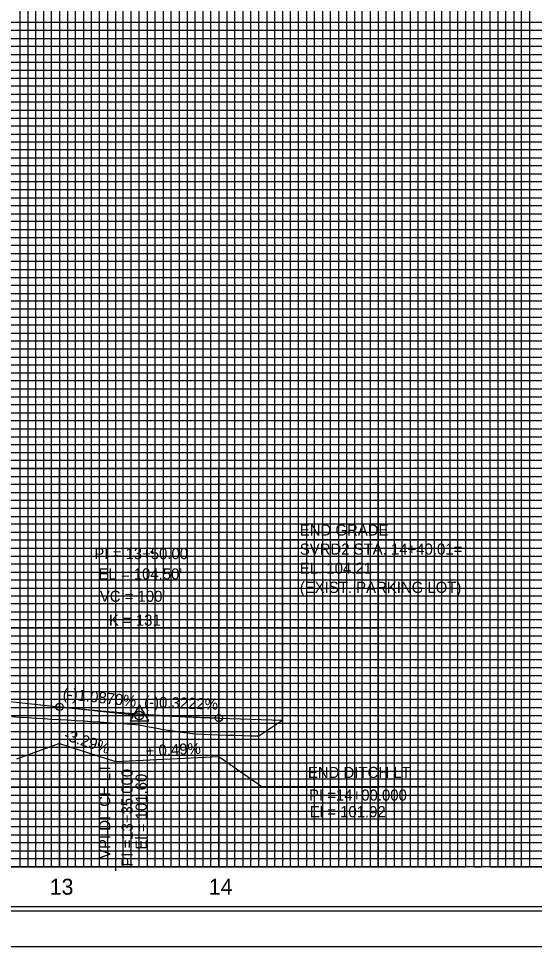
# Model space of a CAD drawing. Extents: x 2345490 to 2436403, y 465165 to 573888.
# Drawn here: x 2382041 to 2382365, y 505721 to 506304 of the extents above; entities that cross this region are included whole.
import ezdxf

# ---------------------------------------------------------------- set-up
doc = ezdxf.new("R2010")
doc.units = 0
for name, color, linetype in [('Old_Level_1', 7, 'Continuous'), ('Old_Level_18', 7, 'Continuous'), ('Old_Level_2', 7, 'Continuous'), ('Old_Level_3', 7, 'Continuous'), ('Old_Level_41', 7, 'Continuous'), ('Old_Level_42', 7, 'Continuous'), ('Old_Level_43', 7, 'Continuous'), ('Old_Level_50', 7, 'Continuous'), ('Old_Level_51', 7, 'Continuous'), ('Old_Level_57', 7, 'Continuous'), ('Old_Level_62', 7, 'Continuous'), ('Old_Level_63', 7, 'Continuous')]:
    doc.layers.add(name, color=color, linetype=linetype)

msp = doc.modelspace()

# ---------------------------------------------------------------- linework, layer by layer
at = {"layer": 'Old_Level_1'}
msp.add_lwpolyline([(2382036.799, 505865.4945), (2382041.799, 505865.19775), (2382046.799, 505864.90075), (2382051.799, 505864.60375), (2382056.799, 505864.307), (2382061.799, 505864.00875), (2382066.799, 505863.707), (2382071.799, 505863.40175), (2382076.799, 505863.09325), (2382081.799, 505862.7815), (2382086.799, 505862.46625), (2382091.799, 505862.14775), (2382096.799, 505861.826), (2382101.799, 505861.501), (2382106.799, 505861.17275), (2382111.799, 505860.84125), (2382116.799, 505860.36675), (2382121.799, 505859.38775), (2382126.799, 505858.41025), (2382131.799, 505857.434), (2382136.799, 505856.701), (2382141.799, 505856.06025), (2382146.799, 505855.42125), (2382151.799, 505854.784), (2382156.799, 505854.51025), (2382161.799, 505854.288), (2382166.799, 505854.0705), (2382171.799, 505853.92325), (2382176.799, 505853.7945), (2382181.799, 505853.66675), (2382186.799, 505853.539), (2382191.799, 505853.45), (2382196.799, 505856.8615), (2382201.799, 505860.10025), (2382206.809, 505863.3455)], dxfattribs=at)
at = {"layer": 'Old_Level_18'}
msp.add_lwpolyline([(2383216.79875, 506796.2405), (2381716.79875, 506796.2405), (2381716.79875, 505746.2405), (2383216.79875, 505746.2405)], close=True, dxfattribs=at)
at = {"layer": 'Old_Level_2'}
for p, q in [((2382206.80875, 505863.34525), (2382206.80875, 505976.80745)), ((2382206.80875, 505976.80745), (2382350.00325, 505976.80745)), ((2381931.799, 505886.34925), (2382066.799, 505871.6755)), ((2382066.799, 505871.6755), (2382114.06525, 505866.53775)), ((2382166.799, 505864.62975), (2382119.54775, 505866.152)), ((2382166.799, 505864.62975), (2382206.809, 505863.3405))]:
    msp.add_line(p, q, dxfattribs=at)
msp.add_lwpolyline([(2382110.99325, 505862.7895), (2382122.73575, 505862.7895), (2382116.86475, 505872.91525)], close=True, dxfattribs=at)
for centre, radius in [((2382066.799, 505871.6755), 2.25), ((2382116.799, 505866.2405), 2.75), ((2382116.799, 505866.2405), 2.75), ((2382166.799, 505864.62975), 2.25)]:
    msp.add_circle(centre, radius, dxfattribs=at)
msp.add_spline([(2382066.799, 505871.6755), (2382068.799, 505871.4595), (2382070.799, 505871.24675), (2382072.799, 505871.037), (2382074.799, 505870.83025), (2382076.799, 505870.62675), (2382078.799, 505870.426), (2382080.799, 505870.2285), (2382082.799, 505870.03425), (2382084.799, 505869.84275), (2382086.799, 505869.6545), (2382088.799, 505869.46925), (2382090.799, 505869.287), (2382092.799, 505869.10775), (2382094.799, 505868.93175), (2382096.799, 505868.75875), (2382098.799, 505868.58875), (2382100.799, 505868.42175), (2382102.799, 505868.258), (2382104.799, 505868.09725), (2382106.799, 505867.9395), (2382108.799, 505867.78475), (2382110.799, 505867.633), (2382112.799, 505867.4845), (2382114.799, 505867.339), (2382116.799, 505867.1965), (2382118.799, 505867.05725), (2382120.799, 505866.921), (2382122.799, 505866.7875), (2382124.799, 505866.6575), (2382126.799, 505866.53025), (2382128.799, 505866.40625), (2382130.799, 505866.28525), (2382132.799, 505866.16725), (2382134.799, 505866.05225), (2382136.799, 505865.9405), (2382138.799, 505865.8315), (2382140.799, 505865.72575), (2382142.799, 505865.62325), (2382144.799, 505865.5235), (2382146.799, 505865.427), (2382148.799, 505865.3335), (2382150.799, 505865.243), (2382152.799, 505865.15575), (2382154.799, 505865.0715), (2382156.799, 505864.99), (2382158.799, 505864.912), (2382160.799, 505864.83675), (2382162.799, 505864.76475), (2382164.799, 505864.69575), (2382166.799, 505864.62975)], degree=3, dxfattribs=at)
at = {"layer": 'Old_Level_3'}
for p, q in [((2382066.799, 505848.7405), (2382039.69453, 505838.87528)), ((2382101.799, 505837.2405), (2382101.799, 505768.74632)), ((2382166.799, 505840.4405), (2382193.64102, 505821.64552)), ((2382193.64102, 505821.64552), (2382296.34187, 505821.64552))]:
    msp.add_line(p, q, dxfattribs=at)
msp.add_lwpolyline([(2382066.799, 505848.7405), (2382101.799, 505837.2405), (2382166.799, 505840.4405)], dxfattribs=at)
msp.add_circle((2382124.68378, 505968.93946), 0.5, dxfattribs=at)
at = {"layer": 'Old_Level_41'}
msp.add_line((2383216.79875, 505771.2405), (2381716.79875, 505771.2405), dxfattribs=at)
for points in [[(2382041.79875, 506796.2405), (2382041.79875, 505771.2405), (2382091.79875, 505771.2405), (2382091.79875, 506796.2405)], [(2382066.79875, 506796.2405), (2382066.79875, 505771.2405), (2382116.79875, 505771.2405), (2382116.79875, 506796.2405)], [(2382141.79875, 506796.2405), (2382141.79875, 505771.2405), (2382191.79875, 505771.2405), (2382191.79875, 506796.2405)], [(2382166.79875, 506796.2405), (2382166.79875, 505771.2405), (2382216.79875, 505771.2405), (2382216.79875, 506796.2405)], [(2382241.79875, 506796.2405), (2382241.79875, 505771.2405), (2382291.79875, 505771.2405), (2382291.79875, 506796.2405)], [(2382266.79875, 506796.2405), (2382266.79875, 505771.2405), (2382316.79875, 505771.2405), (2382316.79875, 506796.2405)], [(2382341.79875, 506796.2405), (2382341.79875, 505771.2405), (2382391.79875, 505771.2405)], [(2383216.79875, 506296.2405), (2381716.79875, 506296.2405), (2381716.79875, 506246.2405), (2383216.79875, 506246.2405)], [(2383216.79875, 506196.2405), (2381716.79875, 506196.2405), (2381716.79875, 506146.2405), (2383216.79875, 506146.2405)], [(2383216.79875, 506121.2405), (2381716.79875, 506121.2405), (2381716.79875, 506171.2405), (2383216.79875, 506171.2405)], [(2383216.79875, 506096.2405), (2381716.79875, 506096.2405), (2381716.79875, 506046.2405), (2383216.79875, 506046.2405)], [(2383216.79875, 506021.2405), (2381716.79875, 506021.2405), (2381716.79875, 506071.2405), (2383216.79875, 506071.2405)], [(2383216.79875, 505996.2405), (2381716.79875, 505996.2405), (2381716.79875, 505946.2405), (2383216.79875, 505946.2405)], [(2383216.79875, 505896.2405), (2381716.79875, 505896.2405), (2381716.79875, 505846.2405), (2383216.79875, 505846.2405)], [(2383216.79875, 505821.2405), (2381716.79875, 505821.2405), (2381716.79875, 505871.2405), (2383216.79875, 505871.2405)], [(2383216.79875, 505796.2405), (2381716.79875, 505796.2405)]]:
    msp.add_lwpolyline(points, dxfattribs=at)
at = {"layer": 'Old_Level_42'}
for points in [[(2383216.79875, 506221.2405), (2381716.79875, 506221.2405), (2381716.79875, 506271.2405), (2383216.79875, 506271.2405)], [(2383216.79875, 505921.2405), (2381716.79875, 505921.2405), (2381716.79875, 505971.2405), (2383216.79875, 505971.2405)]]:
    msp.add_lwpolyline(points, dxfattribs=at)
at = {"layer": 'Old_Level_43'}
for points in [[(2382046.79875, 506796.2405), (2382046.79875, 505771.2405), (2382051.79875, 505771.2405), (2382051.79875, 506796.2405)], [(2382056.79875, 506796.2405), (2382056.79875, 505771.2405), (2382061.79875, 505771.2405), (2382061.79875, 506796.2405)], [(2382071.79875, 506796.2405), (2382071.79875, 505771.2405), (2382076.79875, 505771.2405), (2382076.79875, 506796.2405)], [(2382081.79875, 506796.2405), (2382081.79875, 505771.2405), (2382086.79875, 505771.2405), (2382086.79875, 506796.2405)], [(2382096.79875, 506796.2405), (2382096.79875, 505771.2405), (2382111.79875, 505771.2405), (2382111.79875, 506796.2405)], [(2382101.79875, 506796.2405), (2382101.79875, 505771.2405), (2382106.79875, 505771.2405), (2382106.79875, 506796.2405)], [(2382101.79875, 506795.6405), (2382101.79875, 505771.2405), (2382106.79875, 505771.2405), (2382106.79875, 506795.6405)], [(2382121.79875, 506796.2405), (2382121.79875, 505771.2405), (2382126.79875, 505771.2405), (2382126.79875, 506796.2405)], [(2382131.79875, 506796.2405), (2382131.79875, 505771.2405), (2382136.79875, 505771.2405), (2382136.79875, 506796.2405)], [(2382146.79875, 506796.2405), (2382146.79875, 505771.2405), (2382151.79875, 505771.2405), (2382151.79875, 506796.2405)], [(2382156.79875, 506796.2405), (2382156.79875, 505771.2405), (2382161.79875, 505771.2405), (2382161.79875, 506796.2405)], [(2382171.79875, 506796.2405), (2382171.79875, 505771.2405), (2382176.79875, 505771.2405), (2382176.79875, 506796.2405)], [(2382181.79875, 506796.2405), (2382181.79875, 505771.2405), (2382186.79875, 505771.2405), (2382186.79875, 506796.2405)], [(2382196.79875, 506796.2405), (2382196.79875, 505771.2405), (2382201.79875, 505771.2405), (2382201.79875, 506796.2405)], [(2382206.79875, 506796.2405), (2382206.79875, 505771.2405), (2382211.79875, 505771.2405), (2382211.79875, 506796.2405)], [(2382221.79875, 506796.2405), (2382221.79875, 505771.2405), (2382226.79875, 505771.2405), (2382226.79875, 506796.2405)], [(2382231.79875, 506796.2405), (2382231.79875, 505771.2405), (2382236.79875, 505771.2405), (2382236.79875, 506796.2405)], [(2382246.79875, 506796.2405), (2382246.79875, 505771.2405)], [(2382251.79875, 506796.2405), (2382251.79875, 505771.2405), (2382256.79875, 505771.2405), (2382256.79875, 506796.2405), (2382261.79875, 506796.2405), (2382261.79875, 505771.2405), (2382271.79875, 505771.2405), (2382271.79875, 506796.2405), (2382276.79875, 506796.2405), (2382276.79875, 505771.2405), (2382281.79875, 505771.2405), (2382281.79875, 506796.2405), (2382286.79875, 506796.2405), (2382286.79875, 505771.2405)], [(2382296.79875, 505771.2405), (2382296.79875, 506796.2405)], [(2382301.79875, 506796.2405), (2382301.79875, 505771.2405), (2382306.79875, 505771.2405), (2382306.79875, 506796.2405)], [(2382311.79875, 506796.2405), (2382311.79875, 505771.2405), (2382321.79875, 505771.2405), (2382321.79875, 506796.2405)], [(2382326.79875, 506796.2405), (2382326.79875, 505771.2405), (2382326.79875, 505771.2405), (2382331.79875, 505771.2405), (2382331.79875, 506796.2405)], [(2382336.79875, 506796.2405), (2382336.79875, 505771.2405), (2382346.79875, 505771.2405), (2382346.79875, 506796.2405)], [(2382351.79875, 506796.2405), (2382351.79875, 505771.2405), (2382356.79875, 505771.2405), (2382356.79875, 506796.2405)], [(2382361.79875, 506796.2405), (2382361.79875, 505771.2405), (2382371.79875, 505771.2405)], [(2383166.79875, 506301.2405), (2381766.79875, 506301.2405), (2381766.79875, 506291.2405), (2383166.79875, 506291.2405)], [(2383166.79875, 506286.2405), (2381766.79875, 506286.2405), (2381766.79875, 506281.2405), (2383166.79875, 506281.2405)], [(2383166.79875, 506276.2405), (2381766.79875, 506276.2405)], [(2381766.79875, 506266.2405), (2383166.79875, 506266.2405)], [(2383166.79875, 506261.2405), (2381766.79875, 506261.2405), (2381766.79875, 506256.2405), (2383166.79875, 506256.2405)], [(2383166.79875, 506251.2405), (2381766.79875, 506251.2405), (2381766.79875, 506241.2405), (2383166.79875, 506241.2405)], [(2383166.79875, 506236.2405), (2381766.79875, 506236.2405), (2381766.79875, 506231.2405), (2383166.79875, 506231.2405)], [(2383166.79875, 506226.2405), (2381766.79875, 506226.2405), (2381766.79875, 506216.2405), (2383166.79875, 506216.2405)], [(2383166.79875, 506211.2405), (2381766.79875, 506211.2405), (2381766.79875, 506206.2405), (2383166.79875, 506206.2405)], [(2383166.79875, 506201.2405), (2381766.79875, 506201.2405), (2381766.79875, 506191.2405), (2383166.79875, 506191.2405)], [(2383166.79875, 506186.2405), (2381766.79875, 506186.2405), (2381766.79875, 506181.2405), (2383166.79875, 506181.2405)], [(2383166.79875, 506176.2405), (2381766.79875, 506176.2405), (2381766.79875, 506166.2405), (2383166.79875, 506166.2405)], [(2383166.79875, 506161.2405), (2381766.79875, 506161.2405), (2381766.79875, 506156.2405), (2383166.79875, 506156.2405)], [(2383166.79875, 506151.2405), (2381766.79875, 506151.2405), (2381766.79875, 506141.2405), (2383166.79875, 506141.2405)], [(2383166.79875, 506136.2405), (2381766.79875, 506136.2405), (2381766.79875, 506131.2405), (2383166.79875, 506131.2405)], [(2383166.79875, 506126.2405), (2381766.79875, 506126.2405), (2381766.79875, 506116.2405), (2383166.79875, 506116.2405)], [(2383166.79875, 506111.2405), (2381766.79875, 506111.2405), (2381766.79875, 506106.2405), (2383166.79875, 506106.2405)], [(2383166.79875, 506101.2405), (2381766.79875, 506101.2405), (2381766.79875, 506091.2405), (2383166.79875, 506091.2405)], [(2383166.79875, 506086.2405), (2381766.79875, 506086.2405), (2381766.79875, 506081.2405), (2383166.79875, 506081.2405)], [(2383166.79875, 506076.2405), (2381766.79875, 506076.2405), (2381766.79875, 506066.2405), (2383166.79875, 506066.2405)], [(2383166.79875, 506061.2405), (2381766.79875, 506061.2405), (2381766.79875, 506056.2405), (2383166.79875, 506056.2405)], [(2383166.79875, 506051.2405), (2381766.79875, 506051.2405), (2381766.79875, 506041.2405), (2383166.79875, 506041.2405)], [(2383166.79875, 506036.2405), (2381766.79875, 506036.2405), (2381766.79875, 506031.2405), (2383166.79875, 506031.2405)], [(2383166.79875, 506026.2405), (2381766.79875, 506026.2405), (2381766.79875, 506016.2405), (2383166.79875, 506016.2405)], [(2383166.79875, 506011.2405), (2381766.79875, 506011.2405), (2381766.79875, 506006.2405), (2383166.79875, 506006.2405)], [(2383166.79875, 506001.2405), (2381766.79875, 506001.2405), (2381766.79875, 505991.2405), (2383166.79875, 505991.2405)], [(2383166.79875, 505986.2405), (2381766.79875, 505986.2405), (2381766.79875, 505981.2405), (2383166.79875, 505981.2405)], [(2383166.79875, 505976.2405), (2381766.79875, 505976.2405)], [(2381766.79875, 505966.2405), (2383166.79875, 505966.2405)], [(2383166.79875, 505961.2405), (2381766.79875, 505961.2405), (2381766.79875, 505956.2405), (2383166.79875, 505956.2405)], [(2383166.79875, 505951.2405), (2381766.79875, 505951.2405)], [(2381766.79875, 505941.2405), (2383166.79875, 505941.2405)], [(2383166.79875, 505936.2405), (2381766.79875, 505936.2405), (2381766.79875, 505931.2405), (2383166.79875, 505931.2405)], [(2383166.79875, 505926.2405), (2381766.79875, 505926.2405), (2381766.79875, 505916.2405), (2383166.79875, 505916.2405)], [(2383166.79875, 505911.2405), (2381766.79875, 505911.2405), (2381766.79875, 505906.2405), (2383166.79875, 505906.2405)], [(2383166.79875, 505901.2405), (2381766.79875, 505901.2405), (2381766.79875, 505891.2405), (2383166.79875, 505891.2405)], [(2383166.79875, 505886.2405), (2381766.79875, 505886.2405), (2381766.79875, 505881.2405), (2383166.79875, 505881.2405)], [(2383166.79875, 505876.2405), (2381766.79875, 505876.2405), (2381766.79875, 505866.2405), (2383166.79875, 505866.2405)], [(2383166.79875, 505861.2405), (2381766.79875, 505861.2405), (2381766.79875, 505856.2405), (2383166.79875, 505856.2405)], [(2383166.79875, 505851.2405), (2381766.79875, 505851.2405), (2381766.79875, 505841.2405), (2383166.79875, 505841.2405)], [(2383166.79875, 505836.2405), (2381766.79875, 505836.2405), (2381766.79875, 505831.2405), (2383166.79875, 505831.2405)], [(2383166.79875, 505826.2405), (2381766.79875, 505826.2405), (2381766.79875, 505816.2405), (2383166.79875, 505816.2405)], [(2383166.79875, 505811.2405), (2381766.79875, 505811.2405), (2381766.79875, 505806.2405), (2383166.79875, 505806.2405)], [(2383166.79875, 505801.2405), (2381766.79875, 505801.2405), (2381766.79875, 505791.2405), (2383166.79875, 505791.2405)], [(2383166.79875, 505786.2405), (2381766.79875, 505786.2405), (2381766.79875, 505781.2405), (2383166.79875, 505781.2405)], [(2383166.79875, 505776.2405), (2381766.79875, 505776.2405)]]:
    msp.add_lwpolyline(points, dxfattribs=at)
at = {"layer": 'Old_Level_50'}
msp.add_lwpolyline([(2383229.29875, 506798.7905), (2381562.79875, 506798.7905), (2381562.79875, 505743.6905), (2383229.29875, 505743.6905)], close=True, dxfattribs=at)
at = {"layer": 'Old_Level_51'}
msp.add_lwpolyline([(2383233.79875, 506821.2405), (2381549.79875, 506821.2405), (2381549.79875, 505721.2405), (2383233.79875, 505721.2405)], close=True, dxfattribs=at)
at = {"layer": 'Old_Level_57'}
for p, q in [((2381716.79925, 506021.24075), (2382266.79875, 506021.24075)), ((2382066.79875, 505771.24075), (2382066.79875, 506021.24075)), ((2382166.79875, 505771.24075), (2382166.79875, 506021.24075)), ((2382266.79875, 505771.24075), (2382266.79875, 506021.24075)), ((2381716.79925, 505971.24075), (2382266.79875, 505971.24075)), ((2381716.79925, 505921.24075), (2382266.79875, 505921.24075)), ((2381716.79925, 505871.24075), (2382266.79875, 505871.24075)), ((2381716.799, 505821.24075), (2382266.79875, 505821.24075)), ((2381716.79925, 505771.24075), (2382266.79875, 505771.24075))]:
    msp.add_line(p, q, dxfattribs=at)
at = {"layer": 'Old_Level_63'}
msp.add_line((2381766.79875, 505771.2405), (2382206.80625, 505771.2405), dxfattribs=at)

# ---------------------------------------------------------------- texts
at = {"layer": 'Old_Level_2'}
for s, height, p in [('END GRADE', 7.000001, (2382217.56415, 505979.1792)), ('PI = 13+50.00', 7.0000005, (2382088.63653, 505964.36246)), ('SVRD2 STA. 14+40.01=', 7.0000005, (2382217.56415, 505967.1792)), ('EL. 104.21', 7.000001, (2382217.56415, 505955.1792)), ("EL = 104.50'", 7.0000005, (2382091.22453, 505951.61171)), ('(EXIST. PARKING LOT)', 7.0000005, (2382217.56415, 505943.1792)), ("VC = 100'", 7.000001, (2382092.05928, 505937.57646)), ('K = 131', 7.000001, (2382097.75328, 505922.57846))]:
    msp.add_text(s, height=height, dxfattribs=at).set_placement(p)
for s, rotation, p in [('(-)1.0870%', 353.79655278, (2382068.55995, 505876.63073)), ('(-)0.3222%', 358.15464722, (2382119.80496, 505871.32675))]:
    msp.add_text(s, height=7.000001, rotation=rotation, dxfattribs=at).set_placement(p)
at = {"layer": 'Old_Level_3'}
for s, height, rotation, p in [('-3.29%', 7.000001, 341.81095556, (2382068.95547, 505851.20299)), ('+ 0.49%', 7, 2.81843889, (2382121.00943, 505840.45661)), ('VPI DITCH LT', 7.0000005, 90, (2382098.56795, 505776.17574)), ('PI =13+35.000', 7.0000005, 90, (2382112.64559, 505771.30565)), ('El = 101.60', 7.0000005, 90, (2382121.50115, 505782.01782))]:
    msp.add_text(s, height=height, rotation=rotation, dxfattribs=at).set_placement(p)
for s, p in [('END DITCH LT', (2382222.6514, 505826.98785)), ('PI =14+00.000', (2382223.32235, 505812.77257)), ('El = 101.92', (2382223.88303, 505802.33325))]:
    msp.add_text(s, height=7.0000005, dxfattribs=at).set_placement(p)
at = {"layer": 'Old_Level_62'}
for s, p in [('13', (2382060.605, 505753.7405)), ('14', (2382160.4475, 505753.7405))]:
    msp.add_text(s, height=10.000001, dxfattribs=at).set_placement(p)

doc.saveas('drawing.dxf')
